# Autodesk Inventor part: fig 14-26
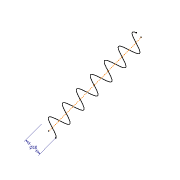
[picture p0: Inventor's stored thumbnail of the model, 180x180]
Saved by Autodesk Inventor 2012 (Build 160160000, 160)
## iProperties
Created: 2007-03
Part Number: fig 14-26
Document SubType Name: Modeling
Designer: Administrator
Density: 1 g/cm^3
Material: Default
Author: Administrator
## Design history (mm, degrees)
node "Sketch1"
sketch "3D Sketch1"
  node "Helical Curve2" dims "d4" = 10, "d5" = 66.31, "d6" = 10, "d7" = 0
